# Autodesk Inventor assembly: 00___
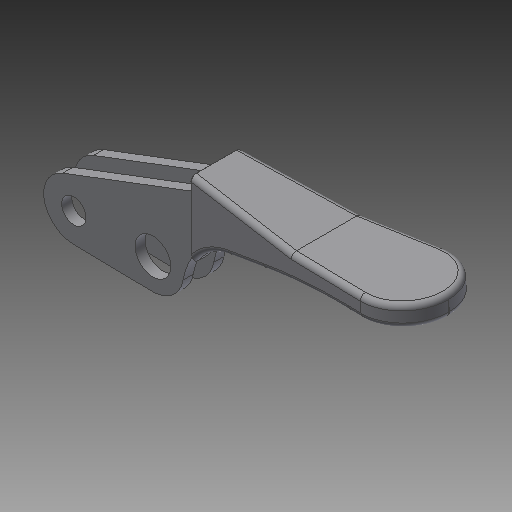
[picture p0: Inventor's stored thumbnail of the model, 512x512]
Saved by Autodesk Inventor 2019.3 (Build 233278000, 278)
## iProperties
Created: 2010-06
Part Number: 00___
Material: Ogólny
Document SubType Name: Assembly
Designer: CADENGINEERING4
Author: CADENGINEERING4
Revision Number: ANY
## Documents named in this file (3)
- D:\Vault_2016\Projekty\Clamptek\STRONA\Latch type clamp\CH-40323\00___.iam
- D:\Vault_2016\Projekty\Clamptek\STRONA\Latch type clamp\CH-40323\_____.ipt
- D:\Vault_2016\Projekty\Clamptek\STRONA\Latch type clamp\CH-40323\àÅ_1___.ipt
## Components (2 placed, 2 different names)
1. ??_??_11
2. àÅ?1_??_12
